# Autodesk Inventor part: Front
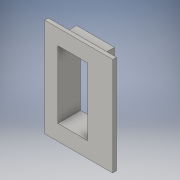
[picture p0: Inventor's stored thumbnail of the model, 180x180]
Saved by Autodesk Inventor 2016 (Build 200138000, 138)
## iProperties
Created: 2015-10
Part Number: Front
Material: Generic
Document SubType Name: Modeling
Designer: ChombaW
Density: 1 g/cm^3
Appearance: Default
Author: ChombaW
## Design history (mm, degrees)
sketch "Sketch1"
  geometry: L1 (22.86, 33.02)-(-22.86, 33.02); L2 (-22.86, 33.02)-(-22.86, -33.02); L3 (-22.86, -33.02)-(22.86, -33.02); L4 (22.86, -33.02)-(22.86, 33.02); L5 (22.86, 33.02)-(-22.86, -33.02); L6 (-22.86, 33.02)-(22.86, -33.02); 1 further point
  constraints: 12 end point, 2 midpoint, 2 parallel, 1 horizontal, 1 perpendicular
  dimensions: "d0" = 45.72 distance of L3.end L2.end; "d1" = 66.04 distance of L2.end L1.end
extrude "Extrusion1" new body sketch "Sketch1" distance "d2" = 2.5146; taper "d3" = 0 deg
sketch "Sketch2"
  geometry: L1 (8.783, -25.4)-(-16.617, -25.4); L2 (-16.617, -25.4)-(-16.617, 25.4); L3 (-16.617, 25.4)-(8.783, 25.4); L4 (8.783, 25.4)-(8.783, -25.4); L5 (8.783, -25.4)-(-16.617, 25.4); L6 (-16.617, -25.4)-(8.783, 25.4); 2 further points
  constraints: 12 end point, 2 midpoint, 2 parallel, 1 horizontal, 1 perpendicular
  dimensions: "d4" = 25.4 distance of L2.end L3.end; "d5" = 50.8 distance of L1.end L2.end
extrude "Extrusion2" join sketch "Sketch2" distance "d6" = 15.24; taper "d7" = 0 deg
sketch "Sketch3"
  geometry: L1 (13.95, -22.606)-(-6.116, -22.606); L2 (-6.116, -22.606)-(-6.116, 22.606); L3 (-6.116, 22.606)-(13.95, 22.606); L4 (13.95, 22.606)-(13.95, -22.606); L5 (13.95, -22.606)-(-6.116, 22.606); L6 (-6.116, -22.606)-(13.95, 22.606); L7 (16.617, 25.4)-(16.617, -25.4) reference; L8 (-8.783, 25.4)-(-8.783, -25.4) reference; 2 further points
  constraints: 12 end point, 2 midpoint, 2 parallel, 1 horizontal, 1 perpendicular
  dimensions: "d8" = 20.066 distance of L2.end L3.end; "d9" = 45.212 distance of L1.end L2.end; "d10" = 2.667 distance between parallel lines of L7 L4; "d11" = 2.667 distance between parallel lines of L2 L8 (derived)
extrude "Extrusion3" cut sketch "Sketch3" distance "d12" = 15.24; taper "d13" = 0 deg
body "Solid1"
